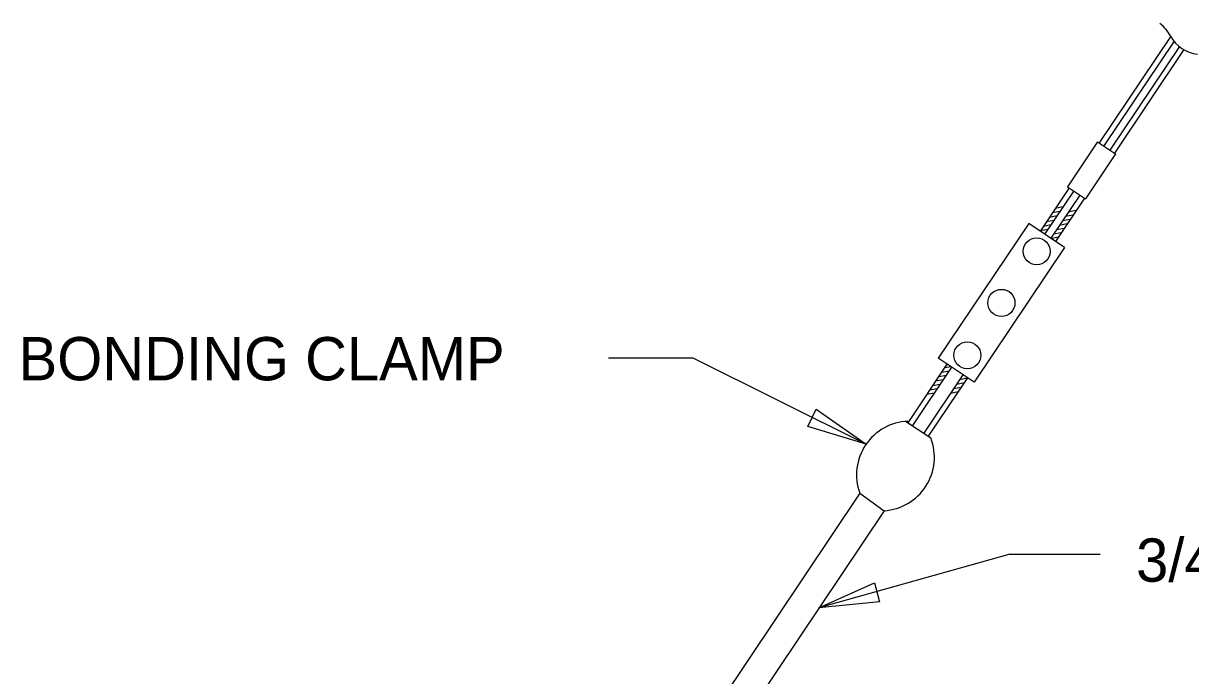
# Model space of a CAD drawing. Extents: x 1299104.8 to 1299141.6, y 239639.8 to 239661.8.
# Drawn here: x 1299114.981 to 1299118.214, y 239647.164 to 239648.972 of the extents above; entities that cross this region are included whole.
import ezdxf

# ---------------------------------------------------------------- set-up
doc = ezdxf.new("R2010")
doc.units = 0
doc.layers.add('DIM TXT', color=7, linetype='Continuous')

msp = doc.modelspace()

# ---------------------------------------------------------------- linework, layer by layer
at = {"layer": 'DIM TXT'}
for p, q in [((1299118.159, 239648.936), (1299117.9611, 239648.6404)), ((1299118.1681, 239648.9226), (1299117.9736, 239648.632)), ((1299118.1829, 239648.9079), (1299117.9906, 239648.6206)), ((1299118.1954, 239648.8992), (1299118.0032, 239648.6121)), ((1299117.9566, 239648.6434), (1299117.873, 239648.5189)), ((1299117.9566, 239648.6434), (1299118.0064, 239648.61)), ((1299118.0064, 239648.61), (1299117.9228, 239648.4855)), ((1299117.8777, 239648.5157), (1299117.7981, 239648.3968)), ((1299117.8902, 239648.5074), (1299117.8105, 239648.3884)), ((1299117.873, 239648.5189), (1299117.9228, 239648.4855)), ((1299117.9072, 239648.4959), (1299117.827, 239648.3762)), ((1299117.9198, 239648.4875), (1299117.8396, 239648.3677)), ((1299117.8522, 239648.4507), (1299117.8314, 239648.4466)), ((1299117.8605, 239648.4631), (1299117.8397, 239648.459)), ((1299117.8877, 239648.4405), (1299117.8671, 239648.4364)), ((1299117.8958, 239648.4528), (1299117.8752, 239648.4487)), ((1299117.7656, 239648.4174), (1299117.5148, 239648.0438)), ((1299117.8652, 239648.3505), (1299117.7656, 239648.4174)), ((1299117.8272, 239648.4133), (1299117.8064, 239648.4092)), ((1299117.8355, 239648.4258), (1299117.8148, 239648.4217)), ((1299117.8439, 239648.4382), (1299117.8231, 239648.4341)), ((1299117.8715, 239648.4159), (1299117.8509, 239648.4118)), ((1299117.8796, 239648.4282), (1299117.859, 239648.4241)), ((1299117.8189, 239648.4009), (1299117.7981, 239648.3968)), ((1299117.8472, 239648.379), (1299117.8266, 239648.3749)), ((1299117.8553, 239648.3913), (1299117.8347, 239648.3872)), ((1299117.8634, 239648.4036), (1299117.8428, 239648.3995)), ((1299117.8652, 239648.3505), (1299117.6144, 239647.9769)), ((1299116.6015, 239648.0449), (1299116.8354, 239648.0449)), ((1299116.8354, 239648.0449), (1299117.3153, 239647.8054)), ((1299117.5393, 239648.0273), (1299117.4306, 239647.8648)), ((1299117.6144, 239647.9769), (1299117.5148, 239648.0438)), ((1299117.5339, 239648.0177), (1299117.5493, 239648.0204)), ((1299117.5518, 239648.0189), (1299117.4434, 239647.8569)), ((1299117.5832, 239647.9978), (1299117.4748, 239647.8358)), ((1299117.5959, 239647.9893), (1299117.4875, 239647.8274)), ((1299117.5168, 239647.9931), (1299117.5377, 239647.9968)), ((1299117.5254, 239648.0054), (1299117.5462, 239648.0091)), ((1299117.5744, 239647.9846), (1299117.5951, 239647.9891)), ((1299117.5825, 239647.9972), (1299117.5836, 239647.9974)), ((1299117.4911, 239647.9562), (1299117.5119, 239647.9599)), ((1299117.4996, 239647.9685), (1299117.5205, 239647.9722)), ((1299117.5082, 239647.9808), (1299117.5291, 239647.9845)), ((1299117.5581, 239647.9594), (1299117.5788, 239647.9639)), ((1299117.5662, 239647.972), (1299117.587, 239647.9765)), ((1299117.4825, 239647.9439), (1299117.5034, 239647.9476)), ((1299117.55, 239647.9468), (1299117.5707, 239647.9513)), ((1299117.4246, 239647.8688), (1299117.4948, 239647.8226)), ((1299117.2976, 239647.6699), (1299115.8601, 239645.522)), ((1299117.2976, 239647.6699), (1299117.365, 239647.6209)), ((1299117.365, 239647.6209), (1299115.9275, 239645.4731)), ((1299117.7104, 239647.5001), (1299117.1846, 239647.3514)), ((1299117.9635, 239647.5001), (1299117.7104, 239647.5001))]:
    msp.add_line(p, q, dxfattribs=at)
for points in [[(1299117.1534, 239647.854), (1299117.1773, 239647.9029), (1299117.3153, 239647.8054)], [(1299117.3388, 239647.4208), (1299117.3528, 239647.3683), (1299117.1846, 239647.3514)]]:
    msp.add_lwpolyline(points, close=True, dxfattribs=at)
for centre in [(1299117.7876, 239648.34), (1299117.6901, 239648.1971), (1299117.5957, 239648.0519)]:
    msp.add_circle(centre, 0.0375, dxfattribs=at)
for centre, radius, start, end in [((1299118.0466, 239648.8725), 0.1291, 29.5211, 50.4106), ((1299118.2456, 239648.9852), 0.0996, 209.5211, 262.7313), ((1299117.4376, 239647.7205), 0.1488, 92.5413, 199.8698), ((1299117.3557, 239647.7695), 0.1488, 273.5762, 20.9047)]:
    msp.add_arc(centre, radius, start, end, dxfattribs=at)

# ---------------------------------------------------------------- texts
for s, p in [('BONDING CLAMP', (1299114.9679, 239647.9824)), ('3/4" ANCHOR ROD', (1299118.0631, 239647.4242))]:
    msp.add_text(s, height=0.12, dxfattribs=at).set_placement(p)

doc.saveas('drawing.dxf')
